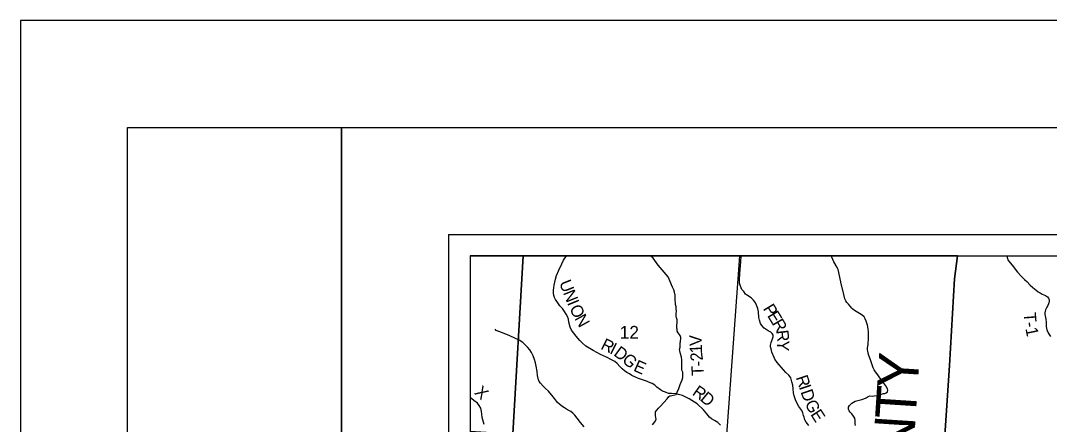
# Model space of a CAD drawing. Extents: x 0 to 34, y 0 to 22.
# Drawn here: x 0 to 4.807, y 20.111 to 22 of the extents above; entities that cross this region are included whole.
import ezdxf

# ---------------------------------------------------------------- set-up
doc = ezdxf.new("R2010")
doc.units = 0
for name, color, linetype in [('GM_X_Corporation', 7, 'Continuous'), ('GM_X_County_Road', 7, 'Continuous'), ('GM_X_County_Road_Text', 7, 'Continuous'), ('GM_X_County_Text', 7, 'Continuous'), ('GM_X_Section_Text', 7, 'Continuous'), ('GM_X_Township_Road', 7, 'Continuous'), ('GM_X_Township_Road_Text', 7, 'Continuous'), ('GM_X_Township_Text', 7, 'Continuous'), ('SH_Border', 7, 'Continuous'), ('SH_Cut_Line', 7, 'Continuous'), ('SH_Data', 7, 'Continuous')]:
    doc.layers.add(name, color=color, linetype=linetype)

msp = doc.modelspace()

# ---------------------------------------------------------------- linework, layer by layer
at = {"layer": 'GM_X_Corporation'}
for points in [[(2.3483, 20.9), (2.1, 20.9), (2.1, 20.0805), (2.3005, 20.0682)], [(3.3608, 20.9), (2.3483, 20.9), (2.3005, 20.0682), (3.2948, 19.9968)]]:
    msp.add_lwpolyline(points, close=True, dxfattribs=at)
msp.add_lwpolyline([(4.1215, 17.0136), (4.1603, 17.6679), (4.1853, 18.0392), (4.1964, 18.2095), (4.2079, 18.3668), (4.2088, 18.3789), (4.2282, 18.6426), (4.2537, 18.9868), (4.2536, 19.0552), (4.2737, 19.3421), (4.2893, 19.6309), (4.3029, 19.8336), (4.3134, 19.9898), (4.3401, 20.3869), (4.364, 20.7926), (4.3772, 20.9), (2.1, 20.9), (2.1, 14.9497)], dxfattribs=at)
at = {"layer": 'GM_X_County_Road'}
msp.add_lwpolyline([(3.2709, 20.1077), (3.2583, 20.1203), (3.2428, 20.13), (3.2278, 20.1383), (3.2191, 20.1458), (3.2061, 20.1611), (3.1902, 20.1805), (3.1607, 20.2077), (3.1242, 20.2315), (3.0925, 20.2461), (3.0745, 20.2517), (3.0644, 20.2541), (3.0414, 20.2563), (3.0279, 20.2566), (3.0136, 20.2621), (2.9996, 20.2673), (2.9892, 20.2735), (2.9734, 20.2861), (2.9634, 20.2946), (2.9514, 20.3022), (2.9389, 20.308), (2.9244, 20.3139), (2.9055, 20.3208), (2.8873, 20.3264), (2.8728, 20.3322), (2.8559, 20.3411), (2.8446, 20.3475), (2.8326, 20.354), (2.8217, 20.3618), (2.8106, 20.3715), (2.7997, 20.3827), (2.7874, 20.3958), (2.7763, 20.4052), (2.7616, 20.414), (2.7369, 20.4258), (2.7102, 20.4381), (2.6758, 20.4565), (2.6406, 20.4777), (2.6233, 20.4925), (2.6137, 20.5034), (2.5966, 20.5235), (2.5852, 20.5377), (2.5737, 20.5528), (2.5677, 20.5664), (2.5614, 20.5891), (2.5594, 20.6045), (2.555, 20.6165), (2.5496, 20.6271), (2.5414, 20.6391), (2.5314, 20.6529), (2.5203, 20.6658), (2.5098, 20.6803), (2.4989, 20.695), (2.4943, 20.705), (2.4911, 20.7139), (2.4898, 20.7254), (2.4902, 20.7394), (2.4909, 20.7504), (2.4927, 20.7621), (2.4994, 20.7911), (2.5043, 20.808), (2.5149, 20.8327), (2.5285, 20.862), (2.537, 20.8803), (2.5512, 20.8994), (2.5527, 20.9)], dxfattribs=at)
at = {"layer": 'GM_X_Township_Road'}
for points in [[(3.063, 20.6204), (3.0634, 20.6298), (3.0641, 20.6406), (3.0636, 20.6518), (3.0628, 20.6607), (3.06, 20.6719), (3.0584, 20.7008), (3.0583, 20.7157), (3.056, 20.7293), (3.0519, 20.7414), (3.0463, 20.7539), (3.0251, 20.8019), (2.9785, 20.8566), (2.9555, 20.8883), (2.9442, 20.8985), (2.9431, 20.9)], [(3.6834, 20.1072), (3.6712, 20.1215), (3.6647, 20.1333), (3.6606, 20.146), (3.6587, 20.1534), (3.6553, 20.166), (3.6499, 20.1764), (3.6362, 20.1955), (3.6227, 20.2223), (3.6148, 20.2445), (3.6115, 20.2598), (3.6091, 20.2782), (3.6078, 20.2945), (3.6041, 20.3114), (3.5981, 20.3289), (3.589, 20.3425), (3.576, 20.3544), (3.565, 20.3675), (3.5347, 20.4016), (3.5245, 20.417), (3.5214, 20.4248), (3.5107, 20.4493), (3.5069, 20.4644), (3.5036, 20.4744), (3.5046, 20.4825), (3.5071, 20.4942), (3.5137, 20.5119), (3.5161, 20.5218), (3.5158, 20.5294), (3.5117, 20.5363), (3.5048, 20.5428), (3.4926, 20.5494), (3.4747, 20.5611), (3.4634, 20.5738), (3.4573, 20.584), (3.4525, 20.5993), (3.4497, 20.6123), (3.4477, 20.6373), (3.4446, 20.653), (3.4382, 20.6693), (3.4331, 20.6802), (3.424, 20.6932), (3.4137, 20.7034), (3.3971, 20.7146), (3.3877, 20.7208), (3.3785, 20.7326), (3.3699, 20.743), (3.363, 20.7576), (3.3594, 20.7714), (3.3587, 20.7861), (3.3604, 20.8177), (3.365, 20.8724), (3.3667, 20.9)], [(3.8328, 20.7783), (3.8201, 20.8364), (3.8153, 20.8454), (3.8004, 20.8713), (3.7901, 20.8943), (3.7889, 20.9)], [(4.6105, 20.9), (4.6103, 20.8978), (4.6101, 20.8916), (4.6108, 20.8868), (4.6126, 20.8814), (4.6158, 20.8761), (4.6322, 20.8556), (4.6576, 20.8238), (4.6762, 20.8028), (4.6912, 20.789), (4.7019, 20.7797), (4.7175, 20.7622), (4.7298, 20.7512), (4.7445, 20.7392), (4.7547, 20.732), (4.7634, 20.7263), (4.7731, 20.7214), (4.789, 20.715), (4.7984, 20.7083), (4.8033, 20.7021), (4.8063, 20.6947), (4.8058, 20.6877), (4.8044, 20.6804), (4.8028, 20.6753), (4.7994, 20.6681), (4.7952, 20.6599), (4.7888, 20.6476), (4.7867, 20.6409), (4.7855, 20.6341), (4.7856, 20.6262), (4.7874, 20.6195), (4.7908, 20.604), (4.7918, 20.5875), (4.7923, 20.569), (4.7957, 20.554), (4.8005, 20.54), (4.8051, 20.5316), (4.8119, 20.5227)], [(3.873, 20.2005), (3.8834, 20.2108), (3.8999, 20.2197), (3.9124, 20.2233), (3.9309, 20.2279), (3.9403, 20.2305), (3.9503, 20.2353), (3.9609, 20.2419), (3.9686, 20.2447), (3.9783, 20.2443), (3.9882, 20.2445), (4.001, 20.2468), (4.0145, 20.2507), (4.0189, 20.2521), (4.0232, 20.2535), (4.0303, 20.2558), (4.0377, 20.2563), (4.0436, 20.259), (4.0505, 20.2637), (4.0518, 20.2711), (4.0503, 20.2787), (4.042, 20.2924), (4.0194, 20.3229), (4, 20.3496), (3.9938, 20.3577), (3.9877, 20.3674), (3.9842, 20.3756), (3.9724, 20.4096), (3.9617, 20.4389), (3.9589, 20.4534), (3.9576, 20.46), (3.9574, 20.47), (3.9601, 20.4858), (3.9624, 20.5167), (3.9614, 20.5435), (3.9609, 20.5591), (3.9569, 20.5751), (3.9513, 20.5942), (3.9464, 20.606), (3.941, 20.6139), (3.9323, 20.6223), (3.9201, 20.63), (3.8961, 20.6442), (3.8878, 20.6505), (3.8837, 20.6555), (3.8757, 20.6646), (3.8683, 20.6744), (3.8607, 20.6822), (3.8551, 20.6894), (3.8515, 20.6986), (3.8469, 20.7185), (3.8332, 20.7762), (3.8328, 20.7783)], [(3.0644, 20.2541), (3.067, 20.2617), (3.0748, 20.28), (3.0819, 20.2984), (3.0906, 20.3193), (3.094, 20.3314), (3.0937, 20.3468), (3.0935, 20.3553), (3.0903, 20.3659), (3.0893, 20.3807), (3.0893, 20.4019), (3.09, 20.4142), (3.0874, 20.4257), (3.0841, 20.442), (3.0799, 20.4558), (3.0794, 20.4621), (3.0815, 20.4732), (3.0819, 20.4847), (3.0819, 20.4933), (3.0827, 20.4982), (3.0838, 20.5043), (3.0853, 20.5108), (3.0845, 20.5184), (3.0822, 20.5268), (3.0772, 20.5331), (3.072, 20.54), (3.068, 20.5483), (3.067, 20.5562), (3.066, 20.5624), (3.0657, 20.5709), (3.0676, 20.5905), (3.068, 20.6009), (3.0646, 20.6106), (3.0629, 20.618), (3.063, 20.6204)], [(2.6339, 20.0997), (2.6166, 20.1206), (2.6001, 20.1413), (2.5894, 20.1543), (2.5805, 20.1642), (2.5705, 20.1714), (2.5556, 20.1796), (2.541, 20.1885), (2.5289, 20.1967), (2.519, 20.2045), (2.5087, 20.2147), (2.4942, 20.2321), (2.4883, 20.241), (2.466, 20.2666), (2.4522, 20.2802), (2.4413, 20.291), (2.4291, 20.3042), (2.4235, 20.3122), (2.4195, 20.3206), (2.4159, 20.3402), (2.4133, 20.3589), (2.4095, 20.3844), (2.4057, 20.4), (2.4009, 20.4149), (2.3944, 20.433), (2.3871, 20.4479), (2.3793, 20.4597), (2.3684, 20.4728), (2.3577, 20.4843), (2.3459, 20.4948), (2.3299, 20.5055), (2.2852, 20.5255), (2.2511, 20.5397), (2.2222, 20.5511), (2.2167, 20.5564)], [(2.1657, 20.1113), (2.1574, 20.1434), (2.1549, 20.1588), (2.1537, 20.1726), (2.1497, 20.1871), (2.1419, 20.2007), (2.1342, 20.2109), (2.1184, 20.2242), (2.1, 20.2378)], [(2.967, 20.1518), (2.9668, 20.1529), (2.9663, 20.1624), (2.9671, 20.17), (2.9727, 20.1779), (2.9813, 20.1878), (2.9898, 20.1973), (3.0208, 20.2314), (3.0294, 20.2421), (3.0339, 20.2448), (3.0423, 20.2463), (3.0569, 20.2496), (3.0624, 20.2512), (3.0644, 20.2541)], [(3.901, 20.1065), (3.9002, 20.1144), (3.8992, 20.1304), (3.8971, 20.141), (3.8911, 20.1503), (3.8831, 20.1606), (3.876, 20.1684), (3.8712, 20.1758), (3.8683, 20.1833), (3.8678, 20.1915), (3.8722, 20.1998), (3.873, 20.2005)], [(2.9532, 20.1096), (2.9634, 20.1243), (2.9691, 20.1343), (2.9686, 20.144), (2.967, 20.1518)]]:
    msp.add_lwpolyline(points, dxfattribs=at)
at = {"layer": 'GM_X_Township_Text'}
msp.add_lwpolyline([(4.3772, 20.9), (4.364, 20.7926), (4.3401, 20.3869), (4.3134, 19.9898), (4.3029, 19.8336), (4.2893, 19.6309), (4.2737, 19.3421), (4.2536, 19.0552), (4.2537, 18.9868), (4.2282, 18.6426), (4.2088, 18.3789), (4.2079, 18.3668), (4.1964, 18.2095), (4.1853, 18.0392), (4.1603, 17.6679), (4.1215, 17.0136)], dxfattribs=at)
at = {"layer": 'SH_Border'}
for points in [[(0.5, 21.5), (1.5, 21.5), (1.5, 0.5), (0.5, 0.5)], [(1.5, 21.5), (33.5, 21.5), (33.5, 0.5), (1.5, 0.5)]]:
    msp.add_lwpolyline(points, close=True, dxfattribs=at)
at = {"layer": 'SH_Cut_Line'}
msp.add_lwpolyline([(0, 0), (34, 0), (34, 22), (0, 22)], close=True, dxfattribs=at)
at = {"layer": 'SH_Data'}
for p, q in [((2, 21), (9, 21)), ((2, 21), (2, 14)), ((2.1, 20.9), (2.1, 14.1)), ((2.1, 20.9), (8.9, 20.9))]:
    msp.add_line(p, q, dxfattribs=at)

# ---------------------------------------------------------------- texts
at = {"layer": 'GM_X_County_Road_Text'}
for s, rotation, p in [('U', 291.5674, (2.5153, 20.7742)), ('N', 291.6163, (2.5337, 20.7276)), ('I', 292.5335, (2.5525, 20.6802)), ('O', 295.873, (2.5629, 20.6554)), ('N', 299.1158, (2.5864, 20.6073)), ('R', 333.9621, (2.7068, 20.4661)), ('I', 333.3721, (2.7486, 20.4457)), ('D', 323.8572, (2.7673, 20.4365)), ('G', 317.9299, (2.8065, 20.408)), ('E', 335.7341, (2.8597, 20.364)), ('R', 324.8603, (3.1342, 20.2522)), ('D', 320.2439, (3.1714, 20.2261))]:
    msp.add_text(s, height=0.0568, rotation=rotation, dxfattribs=at).set_placement(p)
at = {"layer": 'GM_X_County_Text'}
for s, rotation, p in [('Y', 86.2856, (4.1904, 20.2726)), ('T', 86.285, (4.1813, 20.1313)), ('N', 86.285, (4.1704, 19.9641))]:
    msp.add_text(s, height=0.1894, rotation=rotation, dxfattribs=at).set_placement(p)
at = {"layer": 'GM_X_Section_Text'}
msp.add_text('12', height=0.06, rotation=0, dxfattribs=at).set_placement((2.7999, 20.5122))
at = {"layer": 'GM_X_Township_Road_Text'}
for s, rotation, p in [('P', 301.2751, (3.4669, 20.6534)), ('E', 301.2717, (3.4868, 20.6206)), ('T', 274.6248, (4.687, 20.6331)), ('R', 300.3888, (3.5088, 20.5845)), ('-', 276.9198, (4.6907, 20.5883)), ('V', 91.9675, (3.1831, 20.48)), ('R', 276.4458, (3.5304, 20.5502)), ('1', 281.6376, (4.6943, 20.5601)), ('1', 92.2904, (3.1845, 20.4451)), ('Y', 267.5076, (3.5356, 20.5061)), ('2', 97.6572, (3.189, 20.4118)), ('T', 91.8346, (3.1923, 20.3398)), ('-', 93.2943, (3.1908, 20.3838)), ('R', 288.5325, (3.6213, 20.3313)), ('X', 316.7157, (2.117, 20.2572)), ('I', 288.5317, (3.6361, 20.287)), ('D', 289.0989, (3.6437, 20.2643)), ('G', 295.9401, (3.6629, 20.2102)), ('E', 302.9715, (3.6885, 20.1586))]:
    msp.add_text(s, height=0.0568, rotation=rotation, dxfattribs=at).set_placement(p)

doc.saveas('drawing.dxf')
